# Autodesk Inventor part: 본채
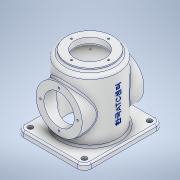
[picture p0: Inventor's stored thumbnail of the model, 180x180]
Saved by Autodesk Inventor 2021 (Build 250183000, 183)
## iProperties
Created: 2021-02
Part Number: 본채
Material: 알루미늄 6061
Document SubType Name: Modeling
Designer: 201-20
Density: 2.7 g/cm^3
Appearance: 알루미늄 - 평지
Author: 201-20
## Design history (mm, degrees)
sketch "스케치1"
  geometry: L1 (70, 60)-(-70, 60); L2 (-70, 60)-(-70, -60); L3 (-70, -60)-(70, -60); L4 (70, -60)-(70, 60); L5 (70, 60)-(-70, -60); L6 (-70, 60)-(70, -60); 1 further point
  constraints: 12 end point, 3 midpoint, 2 parallel, 1 horizontal, 1 perpendicular
  dimensions: "d1" = 140 distance of L3.end L2.end; "d2" = 120 distance of L2.end L1.end
extrude "돌출1" new body sketch "스케치1" distance "d3" = 10; taper "d4" = 0 deg
sketch "스케치2"
  geometry: C1 r 50 at (0, 0); 1 further point
  constraints: 1 centre point, 1 coincident
  dimensions: "d5" = 100 diameter of C1
extrude "돌출2" join sketch "스케치2" distance "d6" = 120; taper "d7" = 0 deg
sketch "스케치3"
  geometry: 1 further point
fillet "모깎기1" dims "d8" = 12
sketch "스케치4"
  geometry: A1 r 12 centre (-58, 48) between (-58, 60) and (-70, 48) reference; 1 further point
sketch "스케치5"
  geometry: C1 r 42 at (0, 0); 1 further point
  constraints: 1 centre point, 1 coincident
  dimensions: "d9" = 84 diameter of C1
extrude "돌출3" cut sketch "스케치5" distance "d10" = 112; taper "d11" = 0 deg
sketch "스케치6"
  geometry: C1 r 41 at (0, 0); 1 further point
  constraints: 1 centre point, 1 coincident
  dimensions: "d12" = 82 diameter of C1
extrude "돌출4" join sketch "스케치6" distance "d13" = 5; taper "d14" = 0 deg
sketch "스케치7"
  geometry: C1 r 27 at (0, 0); 1 further point
  constraints: 1 centre point, 1 coincident
  dimensions: "d15" = 54 diameter of C1
extrude "돌출5" cut sketch "스케치7" extent not by distance; stored distance "d16" = 5; taper "d17" = 0 deg
sketch "스케치8"
  geometry: A1 r 33 centre (0, 0) between (0, 33) and (-33, 0); 3 further points
  constraints: 4 point on circle, 1 centre point, 1 coincident
  dimensions: "d18" = 66 diameter of A1
node "작업점1"
hole "구멍1" sketch "스케치8" diameter "d19" = 3.242; stored, may be unused: countersink angle "d23" = 90 deg, drill point angle "d25" = 118 deg; dims "d20" = 8, "d21" = 4, "d22" = 2, "d24" = 10
node "작업 평면3"
sketch "스케치10"
  geometry: L1 (0, 48)-(0, -48) reference; L2 (-25, 0)-(150, 0) reference; C1 r 41 at (60, 0); 1 further point
  constraints: 1 centre point, 1 point on line
  dimensions: "d36" = 82 diameter of C1; "d37" = 60 distance from line of L1 C1.centre
extrude "돌출7" join sketch "스케치10" stored distance "d38" = 5; taper "d39" = 0 deg; dims "d82" = 0
sketch "스케치11"
  geometry: C1 r 41 at (0, 0) reference; C2 r 27 at (0, 0); 1 further point
  constraints: 1 centre point, 1 coincident
  dimensions: "d40" = 54 diameter of C2
extrude "돌출8" cut sketch "스케치11" extent not by distance; stored distance "d41" = 0; taper "d42" = 0 deg
sketch "스케치12"
  geometry: C1 r 27 at (0, 0) reference; C2 r 41 at (0, 0) reference; A1 r 33 centre (0, 0) between (0, 33) and (-33, 0); 3 further points
  constraints: 4 point on circle, 1 centre point, 1 coincident
  dimensions: "d43" = 66 diameter of A1
hole "구멍2" sketch "스케치12" at (0, 33), (33, 0), (0, -33), (-33, 0) diameter "d44" = 3.242; stored, may be unused: countersink angle "d48" = 90 deg, drill point angle "d50" = 118 deg; dims "d45" = 8, "d46" = 4, "d47" = 2, "d49" = 10
sketch "스케치13"
  geometry: C1 r 41 at (0, 0) reference; C2 r 33 at (0, 0); C3 r 1.621 at (0, 33) reference; C4 r 1.621 at (-33, 0) reference; C5 r 1.621 at (0, -33) reference; C6 r 1.621 at (33, 0) reference; 5 further points
  constraints: 5 coincident, 1 centre point
  dimensions: "d51" = 66 diameter of C2
hole "구멍3" sketch "스케치13" at (0, 33), (33, 0), (0, -33), (-33, 0) diameter "d52" = 3.242; stored, may be unused: countersink angle "d56" = 90 deg, drill point angle "d58" = 118 deg; dims "d53" = 8, "d54" = 4, "d55" = 2, "d57" = 10
fillet "모깎기2" dims "d59" = 3
fillet "모깎기3" dims "d60" = 6
fillet "모깎기4" dims "d61" = 3
fillet "모깎기5" dims "d62" = 3
fillet "모깎기6" dims "d63" = 3
sketch "스케치15"
  geometry: A1 r 12 centre (-58, 48) between (-58, 60) and (-70, 48) reference; A2 r 12 centre (58, 48) between (70, 48) and (58, 60) reference; A3 r 12 centre (58, -48) between (58, -60) and (70, -48) reference; A4 r 12 centre (-58, -48) between (-70, -48) and (-58, -60) reference; 1 further point
hole "구멍4" sketch "스케치15" at (-58, 48), (-58, -48) diameter "d65" = 9; stored, may be unused: countersink angle "d69" = 90 deg, drill point angle "d71" = 118 deg; dims "d66" = 8, "d67" = 4, "d68" = 2, "d70" = 10
sketch "스케치16"
  geometry: A1 r 12 centre (58, 48) between (70, 48) and (58, 60) reference; A2 r 12 centre (58, -48) between (58, -60) and (70, -48) reference; 1 further point
hole "구멍5" sketch "스케치16" at (58, 48), (58, -48) diameter "d72" = 9; stored, may be unused: countersink angle "d76" = 90 deg, drill point angle "d78" = 118 deg; dims "d73" = 8, "d74" = 4, "d75" = 2, "d77" = 10
node "작업 평면4"
sketch "스케치17"
  geometry: 2 further points
  constraints: 1 other
  dimensions: "d80" = 66 vertical distance of point (0.168, 66) point (0, 0)
feature "엠보싱2" sketch "스케치17" dims "d1" = 140, "d2" = 120, "d81" = 0.5, "d82" = 0
fillet "모깎기7" dims "d83" = 3
node "솔리드1"
mirror "미러3"
node "투영된 루프1"
node "투영된 루프2"
feature "A9D066F2-1C7D-4E18-AEED-F7BC21143FA4" dims "d65" = 9, "d66" = 8, "d67" = 4, "d68" = 2, "d69" = 90 deg, "d70" = 10, "d71" = 118 deg
other parameters: "d33" = 55, "d79" = -72.5
